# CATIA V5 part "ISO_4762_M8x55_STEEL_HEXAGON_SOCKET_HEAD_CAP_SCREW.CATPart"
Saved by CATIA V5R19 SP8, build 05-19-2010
Part number: ISO 4762 SCREW M8x55 STEEL HEXAGON SOCKET HEAD CAP
Nomenclature: 25
Publications: "Mating Face", "Axis"
Bounding box of the stored display mesh (mm): x -55 to 8, y -6.5 to 6.5, z -6.49 to 6.49
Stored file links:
  C:\Users\rphgr\Desktop\0_Tapis_TC520B_vitesse\ISO_4762_M8x55_STEEL_HEXAGON_SOCKET_HEAD_CAP_SCREW.CATPart
  D:\Programmes\DassaultSysteme\win_b64\startup\components\MechanicalStandardParts\EN_Standards\Design_Tables\EN_ISO_4762_HEXAGON_SOCKET_HEAD_CAP_SCREW.txt
  C:\Program Files\Dassault Systemes\B19\win_b64\startup\components\MechanicalStandardParts\ISO_Standards\Design_Tables\ISO_4762_HEXAGON_SOCKET_HEAD_CAP_SCREW.txt
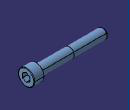
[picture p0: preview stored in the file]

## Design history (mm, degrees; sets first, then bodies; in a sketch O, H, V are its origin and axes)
Parameters
  d_dia = 8 mm
  l_nom = 55 mm
  k_head_depth_max = 8 mm
  s_nom = 6 mm
  r_min = 0.4 mm
  ds_max = 8 mm
  e = 6.863 mm
  t_min = 4 mm
  p_pitch = 1.25 mm
  Threading = 28 mm
  dk_max = 13 mm
Body1 "PartBody" (main body)
  Sketch1 on yz-plane, origin (0, 0, 0), H (0, 1, 0), V (0, 0, 1)
    circle A1 centre (0, 0) radius 6.5
    radius A1 = 6.5 {= dk_max /2}
  Pad1: profile Sketch1, direction (1, 0, 0), length 8 {= k_head_depth_max}
  Fillet1: radius 0.4 {= r_min}, on edge [face of Pad1 | face of Pad1]
  Body2
    Sketch2 on face of Pad1, origin (8, 0, 0), H (0, 1, 0), V (0, 0, 1)
      point P1 (3, -1.7321)
      point P2 (3, 1.7321)
      point P3 (0, 3.4641)
      point P4 (-3, 1.7321)
      point P5 (-3, -1.7321)
      point P6 (0, -3.4641)
      point P7 (3, 0)
      line L1 (3, -1.7321) -> (3, 1.7321)
      line L2 (3, 1.7321) -> (0, 3.4641)
      line L3 (0, 3.4641) -> (-3, 1.7321)
      line L4 (-3, 1.7321) -> (-3, -1.7321)
      line L5 (-3, -1.7321) -> (0, -3.4641)
      line L6 (0, -3.4641) -> (3, -1.7321)
      construction line L7 (0, 0) -> (3, 0)
      construction circle A1 centre (0, 0) radius 3.4641
      construction arc A2 centre (-3, -1.7321) radius 3.4641 from (-3, 1.7321) to (0, -3.4641) cw
      construction arc A3 centre (3, 1.7321) radius 3.4641 from (0, 3.4641) to (3, -1.7321) ccw
      point P8 (-3, -1.7321)
      point P9 (3, 1.7321)
      distance L1 L4 = 6 {= s_nom}
      horizontal: L7 H
      coincidence: A1 P1, A1 P2, A1 P3, A1 P4, A1 P5, A1 P6, A2 P4, A2 P6, A2 O, P8 P5, A3 P3, A3 P1, A3 O, P9 P2
      midpoint: P7 L1
    Pad2: profile Sketch2, direction (-1, 0, 0), length 5.9778 {= t_min +(e /3.47)}
    Body3
      Sketch3 on zx-plane, origin (0, 0, 0), H (-1, 0, 0), V (0, 0, 1)
        point P1 (-2.0188, 0)
        line L1 (-2.0188, 0) -> (-4, 3.4315)
        line L2 (-4, 3.4315) -> (-8, 3.4315)
        line L3 (-8, 3.4315) -> (-8, 0)
        axis line L4 (-46.2384, 0) -> (26.3409, 0)
        reference projected line E1 (-8, -6.9227) -> (-8, 6.9227) from edge [face of Pad2 | face of Pad2]
        length L2 = 4 {= t_min}
        angle L1 L4 = 60
        distance L2 L4 = 3.4315 {= e /2}
        horizontal: L2 H, L4 H
        perpendicularity: L3 L2
        fix: L4
        coincidence: L3 E1, P1 L4
      Shaft1: profile Sketch3, axis Sketch3.L4, angle 360
    Intersect1: tool Body3
  Remove1: tool Body2
  Sketch4 on xy-plane, origin (0, 0, 0), H (1, 0, 0), V (0, 1, 0)
    line L1 (0, 0) -> (0, 4)
    line L2 (0, 4) -> (-27, 4)
    line L3 (-27, 4) -> (-27, 3.9024)
    line L4 (-27, 3.9024) -> (-55, 3.9024)
    line L5 (-55, 3.9024) -> (-55, 0)
    axis line L6 (-192.3446, 0) -> (99.1594, 0)
    distance L5 L1 = 55 {= l_nom}
    distance L3 L5 = 28 {= Threading}
    distance L2 L6 = 4 {= ds_max /2}
    distance L4 L6 = 3.9024 {= d_dia /2.05}
    vertical: L1 V, L3 V, L5 V
    horizontal: L2 H, L4 H, L6 H
    fix: L6
  Shaft2: profile Sketch4, axis Sketch4.L6, angle 360
  Fillet2: radius 0.4 {= r_min}, on edge [face of Shaft2 | face of Pad1]
  Chamfer1: length 1.25 {= p_pitch}, angle 45, on edge [face of Shaft2 | face of Shaft2]
  Thread1: diameter 7.8049 {= d_dia /1.025}, depth 28 {= Threading}, pitch 1, on face of Shaft2, from face of Shaft2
